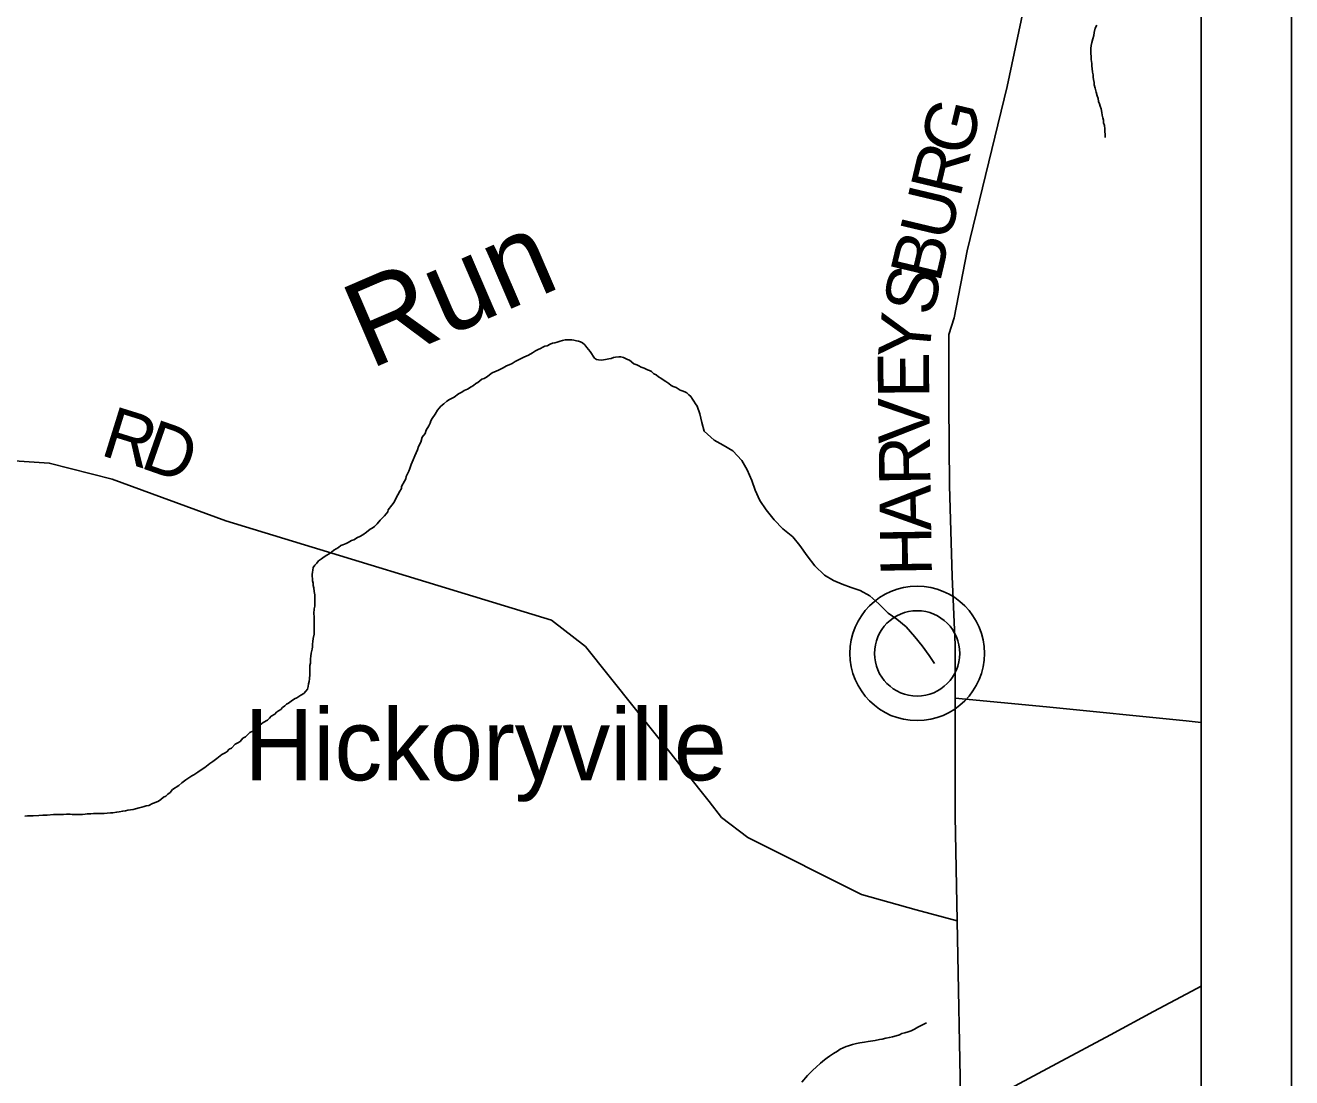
# Model space of a CAD drawing. Extents: x 0.4 to 34.4, y -2.1 to 19.9.
# Drawn here: x 8.499 to 9.9, y 16.558 to 17.722 of the extents above; entities that cross this region are included whole.
import ezdxf

# ---------------------------------------------------------------- set-up
doc = ezdxf.new("R2010")
doc.units = 0
for name, color, linetype in [('GM_X_County', 7, 'Continuous'), ('GM_X_County_Road', 7, 'Continuous'), ('GM_X_County_Road_Text', 7, 'Continuous'), ('GM_X_Interstate_Route', 7, 'Continuous'), ('GM_X_Minor_River', 7, 'Continuous'), ('GM_X_Minor_River_Text', 7, 'Continuous'), ('GM_X_Township', 7, 'Continuous'), ('GM_X_Township_Road', 7, 'Continuous'), ('GM_X_Township_Road_Text', 7, 'Continuous'), ('GM_X_Unincorporated', 7, 'Continuous'), ('GM_X_Unincorporated_Text', 7, 'Continuous'), ('SH_Data', 7, 'Continuous')]:
    doc.layers.add(name, color=color, linetype=linetype)

msp = doc.modelspace()

# ---------------------------------------------------------------- linework, layer by layer
at = {"layer": 'GM_X_County'}
msp.add_lwpolyline([(9.8001, 15.3423), (9.8001, 18.8357), (3.0001, 18.8357), (3.0001, 12.0357), (9.5074, 12.0357)], dxfattribs=at)
at = {"layer": 'GM_X_County_Road'}
msp.add_lwpolyline([(9.5341, 16.5199), (9.53, 16.7315), (9.5277, 16.8475), (9.5276, 16.9397), (9.5276, 16.978), (9.5276, 17.0369), (9.5243, 17.1124), (9.5213, 17.2134), (9.5205, 17.3038), (9.5205, 17.3801), (9.5265, 17.3986), (9.5409, 17.4727), (9.5854, 17.6546), (9.6059, 17.7522)], dxfattribs=at)
at = {"layer": 'GM_X_Interstate_Route'}
msp.add_lwpolyline([(9.5885, 16.5462), (9.6403, 16.5738), (9.6997, 16.6054), (9.7473, 16.6315), (9.7898, 16.654), (9.8001, 16.6595)], dxfattribs=at)
at = {"layer": 'GM_X_Minor_River'}
for points in [[(9.6843, 17.7226), (9.6827, 17.7192), (9.6815, 17.7142), (9.6811, 17.7112), (9.6799, 17.7074), (9.6791, 17.7033), (9.6783, 17.6999), (9.6779, 17.6968), (9.6778, 17.6942), (9.6778, 17.6911), (9.6781, 17.6877), (9.6781, 17.6843), (9.6788, 17.6801), (9.6791, 17.6771), (9.6794, 17.6744), (9.6798, 17.6706), (9.6805, 17.6676), (9.6804, 17.6649), (9.6808, 17.6622), (9.6815, 17.6592), (9.6815, 17.6565), (9.6826, 17.6527), (9.6836, 17.6485), (9.6847, 17.6443), (9.6858, 17.6413), (9.6865, 17.6382), (9.6876, 17.6356), (9.6883, 17.6329), (9.6891, 17.6299), (9.6901, 17.6257), (9.6905, 17.623), (9.6912, 17.62), (9.6919, 17.6173), (9.6919, 17.6146), (9.693, 17.6116), (9.6933, 17.6078), (9.6933, 17.6051), (9.6936, 17.6013), (9.6936, 17.5983)], [(9.0554, 17.3573), (9.06, 17.3599), (9.0631, 17.3621), (9.0662, 17.3636), (9.0689, 17.3647), (9.0712, 17.3661), (9.0736, 17.3672), (9.0762, 17.3679), (9.0793, 17.3694), (9.082, 17.3705), (9.0847, 17.3712), (9.087, 17.3719), (9.0905, 17.373), (9.0931, 17.3737), (9.0962, 17.3744), (9.0985, 17.3744), (9.1012, 17.3743), (9.1035, 17.3743), (9.1057, 17.3739), (9.1084, 17.3734), (9.1107, 17.373), (9.1129, 17.3722), (9.1152, 17.371), (9.1178, 17.3687), (9.12, 17.366), (9.1219, 17.3637), (9.1238, 17.3614), (9.1252, 17.3591), (9.1271, 17.3564), (9.1285, 17.3541), (9.1308, 17.3525), (9.1331, 17.3521), (9.1357, 17.352), (9.1384, 17.3524), (9.1407, 17.3527), (9.1445, 17.3534), (9.1468, 17.3537), (9.1495, 17.3548), (9.1518, 17.3552), (9.1553, 17.3555), (9.1575, 17.3554), (9.1606, 17.355), (9.1628, 17.3538), (9.1651, 17.3526), (9.1674, 17.3518), (9.1722, 17.3479), (9.1753, 17.3467), (9.1775, 17.3456), (9.1802, 17.344), (9.1836, 17.3432), (9.187, 17.3412), (9.1892, 17.3404), (9.1915, 17.3392), (9.1941, 17.3369), (9.1968, 17.3357), (9.1994, 17.3334), (9.202, 17.3318), (9.2046, 17.3302), (9.2073, 17.3283), (9.2106, 17.3259), (9.2133, 17.324), (9.2155, 17.3228), (9.2189, 17.3216), (9.2212, 17.32), (9.2234, 17.3188), (9.2257, 17.318), (9.2284, 17.3169), (9.2306, 17.3157), (9.2329, 17.3137), (9.2351, 17.3118), (9.2369, 17.3087), (9.2384, 17.3064), (9.2403, 17.3037), (9.2422, 17.301)], [(8.819, 17.0851), (8.8191, 17.0881), (8.8188, 17.0923), (8.8181, 17.0961), (8.8178, 17.0999), (8.8171, 17.1026), (8.8172, 17.1053), (8.8165, 17.1079), (8.8165, 17.1102), (8.8162, 17.1125), (8.8162, 17.1148), (8.8163, 17.1175), (8.8167, 17.1197), (8.8172, 17.1224), (8.8191, 17.125), (8.8211, 17.1273), (8.8231, 17.1299), (8.8265, 17.1321), (8.8293, 17.1343), (8.8323, 17.1362), (8.835, 17.1377), (8.8374, 17.1395), (8.8401, 17.1417), (8.8424, 17.1432), (8.8451, 17.1447), (8.8478, 17.1469), (8.8501, 17.1476), (8.8536, 17.1491), (8.8559, 17.1502), (8.8594, 17.1524), (8.8621, 17.1531), (8.8663, 17.1557), (8.8686, 17.1568), (8.8721, 17.1587), (8.876, 17.1616), (8.8803, 17.165), (8.8826, 17.1661), (8.8849, 17.1679), (8.888, 17.1709), (8.8912, 17.175), (8.8962, 17.1795), (8.8978, 17.1818), (8.8998, 17.184), (8.9002, 17.1863), (8.9041, 17.1915), (8.9069, 17.1949), (8.9089, 17.1994), (8.9109, 17.2028), (8.9129, 17.207), (8.9148, 17.21), (8.9149, 17.2123), (8.9181, 17.2179), (8.9197, 17.2206), (8.9201, 17.2232), (8.9229, 17.2292), (8.9241, 17.2319), (8.9257, 17.2364), (8.9278, 17.2417), (8.9298, 17.2459), (8.931, 17.2493), (8.9326, 17.2527), (8.9338, 17.2564), (8.9362, 17.261), (8.9378, 17.2666), (8.941, 17.2708), (8.9422, 17.2745), (8.945, 17.2791), (8.9466, 17.2821), (8.9474, 17.2847), (8.949, 17.2873), (8.9521, 17.2922), (8.9549, 17.2964), (8.9584, 17.3009), (8.9619, 17.3035), (8.9651, 17.3065), (8.9681, 17.3083), (8.9708, 17.3098), (8.9732, 17.3109), (8.9778, 17.3146), (8.9817, 17.3164), (8.9844, 17.3183), (8.9878, 17.3197), (8.9921, 17.3223), (8.9944, 17.3238), (8.9971, 17.326), (8.9995, 17.3271), (9.0037, 17.3309), (9.0064, 17.3316), (9.0099, 17.3338), (9.0122, 17.3356), (9.0153, 17.3379), (9.0196, 17.3397), (9.0223, 17.3408), (9.0273, 17.3434), (9.0311, 17.3456), (9.0342, 17.3467), (9.0373, 17.3481), (9.0408, 17.3503), (9.045, 17.3525), (9.0504, 17.3551), (9.0554, 17.3573)], [(9.2422, 17.301), (9.2452, 17.2924), (9.2473, 17.2829), (9.2497, 17.2734), (9.2609, 17.2633), (9.271, 17.2578), (9.2815, 17.2515), (9.2915, 17.241), (9.2973, 17.2307), (9.3028, 17.2188), (9.3063, 17.2081), (9.3114, 17.1966), (9.3184, 17.1863), (9.3273, 17.1754), (9.3369, 17.1654), (9.3481, 17.1564), (9.3559, 17.1468), (9.364, 17.1356), (9.3724, 17.1244), (9.3832, 17.114), (9.3929, 17.1081), (9.4027, 17.1041), (9.4125, 17.1005), (9.4227, 17.0972), (9.4331, 17.091), (9.4432, 17.0824), (9.4536, 17.072), (9.4633, 17.0653), (9.4733, 17.0568), (9.483, 17.0459), (9.4911, 17.0359), (9.4988, 17.0251), (9.5049, 17.0164)], [(8.5796, 16.8502), (8.5827, 16.8505), (8.5857, 16.8504), (8.5891, 16.8508), (8.593, 16.8511), (8.5953, 16.851), (8.5995, 16.8517), (8.6025, 16.8524), (8.6064, 16.8531), (8.6094, 16.8534), (8.6121, 16.8541), (8.6148, 16.8545), (8.6178, 16.8548), (8.6205, 16.8555), (8.6247, 16.8566), (8.6274, 16.8573), (8.6301, 16.858), (8.6324, 16.8587), (8.6351, 16.8594), (8.6393, 16.8616), (8.6416, 16.862), (8.6459, 16.8642), (8.6486, 16.866), (8.6513, 16.8686), (8.654, 16.8697), (8.6563, 16.8716), (8.6587, 16.8735), (8.6614, 16.8768), (8.6684, 16.8813), (8.6719, 16.8842), (8.6761, 16.8876), (8.6827, 16.892), (8.685, 16.8931), (8.6893, 16.8961), (8.6943, 16.8994), (8.6974, 16.9013), (8.7029, 16.9057), (8.706, 16.908), (8.7106, 16.9113), (8.716, 16.9158), (8.7191, 16.9172), (8.7215, 16.9187), (8.7242, 16.9217), (8.7269, 16.9228), (8.7308, 16.9269), (8.7339, 16.9284), (8.7362, 16.9302), (8.7393, 16.9336), (8.7424, 16.9351), (8.7471, 16.9399), (8.7502, 16.9414), (8.7533, 16.9451), (8.7556, 16.9466), (8.758, 16.9481), (8.7618, 16.9511), (8.7665, 16.9537), (8.7688, 16.9559), (8.7708, 16.9581), (8.7746, 16.9603), (8.7766, 16.9626), (8.7789, 16.9641), (8.7812, 16.9656), (8.7832, 16.9678), (8.7859, 16.9693), (8.7875, 16.9715), (8.7898, 16.9726), (8.7929, 16.9745), (8.7964, 16.9771), (8.7991, 16.9785), (8.8033, 16.9811), (8.8068, 16.9833), (8.8091, 16.9856), (8.8107, 16.9878), (8.8115, 16.9909), (8.812, 16.9939), (8.8128, 16.9965), (8.8129, 16.9992), (8.8134, 17.0041), (8.8134, 17.0079), (8.8135, 17.0114), (8.8136, 17.014), (8.814, 17.0167), (8.8141, 17.0213), (8.8146, 17.0243), (8.815, 17.0277), (8.8159, 17.0323), (8.8163, 17.0349), (8.8164, 17.0376), (8.8168, 17.0406), (8.8173, 17.044), (8.8182, 17.0489), (8.8183, 17.0528), (8.8184, 17.0569), (8.8184, 17.0607), (8.8181, 17.0638), (8.8182, 17.068), (8.8179, 17.0718), (8.8184, 17.0767), (8.8189, 17.0797), (8.8189, 17.082), (8.819, 17.0851)], [(8.498, 16.8475), (8.501, 16.8478), (8.5037, 16.8478), (8.5071, 16.8477), (8.5136, 16.848), (8.5178, 16.8486), (8.5228, 16.8486), (8.5296, 16.8492), (8.535, 16.8491), (8.538, 16.8494), (8.5407, 16.8494), (8.5441, 16.8497), (8.5483, 16.8496), (8.5506, 16.8492), (8.5571, 16.8494), (8.5617, 16.8494), (8.5647, 16.8497), (8.567, 16.85), (8.5712, 16.8499), (8.5739, 16.8503), (8.5796, 16.8502)], [(9.3579, 16.5532), (9.3644, 16.5607), (9.3702, 16.5663), (9.374, 16.5697), (9.3787, 16.5742), (9.3829, 16.5779), (9.386, 16.5802), (9.3886, 16.582), (9.3932, 16.585), (9.3975, 16.5876), (9.4005, 16.5895), (9.4036, 16.5913), (9.407, 16.5928), (9.4097, 16.5935), (9.4139, 16.595), (9.4185, 16.596), (9.4223, 16.5967), (9.4272, 16.5974), (9.4314, 16.5981), (9.4364, 16.5988), (9.439, 16.5992), (9.444, 16.6002), (9.447, 16.6006), (9.4508, 16.6017), (9.455, 16.6027), (9.4584, 16.6035), (9.4623, 16.6045), (9.4661, 16.6056), (9.4687, 16.6071), (9.4718, 16.6078), (9.4756, 16.6089), (9.479, 16.61), (9.4825, 16.6118), (9.4863, 16.6141), (9.4894, 16.6156), (9.4924, 16.617), (9.4959, 16.6189)]]:
    msp.add_lwpolyline(points, dxfattribs=at)
at = {"layer": 'GM_X_Township'}
msp.add_lwpolyline([(9.8001, 15.535), (9.8001, 18.8357), (6.992, 18.8357)], dxfattribs=at)
at = {"layer": 'GM_X_Township_Road'}
for points in [[(8.3782, 17.7268), (8.3756, 17.6984), (8.3802, 17.6744), (8.3918, 17.5358), (8.3895, 17.5062), (8.3804, 17.476), (8.3775, 17.4544), (8.3829, 17.3404), (8.3876, 17.2618), (8.3936, 17.2515), (8.4083, 17.2456), (8.525, 17.2381), (8.5946, 17.2202), (8.7203, 17.1743), (9.0808, 17.0644), (9.1187, 17.0351), (9.2555, 16.8637), (9.2689, 16.846), (9.2981, 16.824), (9.424, 16.7606), (9.4844, 16.7437), (9.53, 16.7315)], [(9.8001, 16.9509), (9.7832, 16.953), (9.6289, 16.9682), (9.5276, 16.978)]]:
    msp.add_lwpolyline(points, dxfattribs=at)
at = {"layer": 'GM_X_Unincorporated'}
for radius in [0.0744, 0.0472]:
    msp.add_circle((9.4856, 17.0275), radius, dxfattribs=at)
at = {"layer": 'SH_Data'}
for p, q in [((9.9001, 18.9357), (9.9001, 11.9357)), ((9.8001, 18.8357), (9.8001, 12.0357))]:
    msp.add_line(p, q, dxfattribs=at)

# ---------------------------------------------------------------- texts
at = {"layer": 'GM_X_County_Road_Text'}
for s, rotation, p in [('G', 76.6135, (9.5438, 17.5758)), ('R', 76.6084, (9.533, 17.5304)), ('U', 76.6114, (9.5214, 17.4818)), ('B', 76.6207, (9.5106, 17.4364)), ('S', 78.2437, (9.5029, 17.3993)), ('Y', 84.8969, (9.4987, 17.3512)), ('E', 90.3386, (9.499, 17.3101)), ('V', 90.8852, (9.4997, 17.2602)), ('R', 90.8855, (9.5005, 17.2136)), ('A', 90.8843, (9.5012, 17.1636)), ('H', 90.8852, (9.502, 17.1136))]:
    msp.add_text(s, height=0.0568, rotation=rotation, dxfattribs=at).set_placement(p)
at = {"layer": 'GM_X_Minor_River_Text'}
msp.add_text('Run', height=0.09469, rotation=23.2983, dxfattribs=at).set_placement((8.8797, 17.3413))
at = {"layer": 'GM_X_Township_Road_Text'}
for s, rotation, p in [('R', 342.6895, (8.5802, 17.2473)), ('D', 340.6826, (8.6242, 17.2335))]:
    msp.add_text(s, height=0.0568, rotation=rotation, dxfattribs=at).set_placement(p)
at = {"layer": 'GM_X_Unincorporated_Text'}
msp.add_text('Hickoryville', height=0.078977, rotation=0, dxfattribs=at).set_placement((8.741, 16.8871))

doc.saveas('drawing.dxf')
